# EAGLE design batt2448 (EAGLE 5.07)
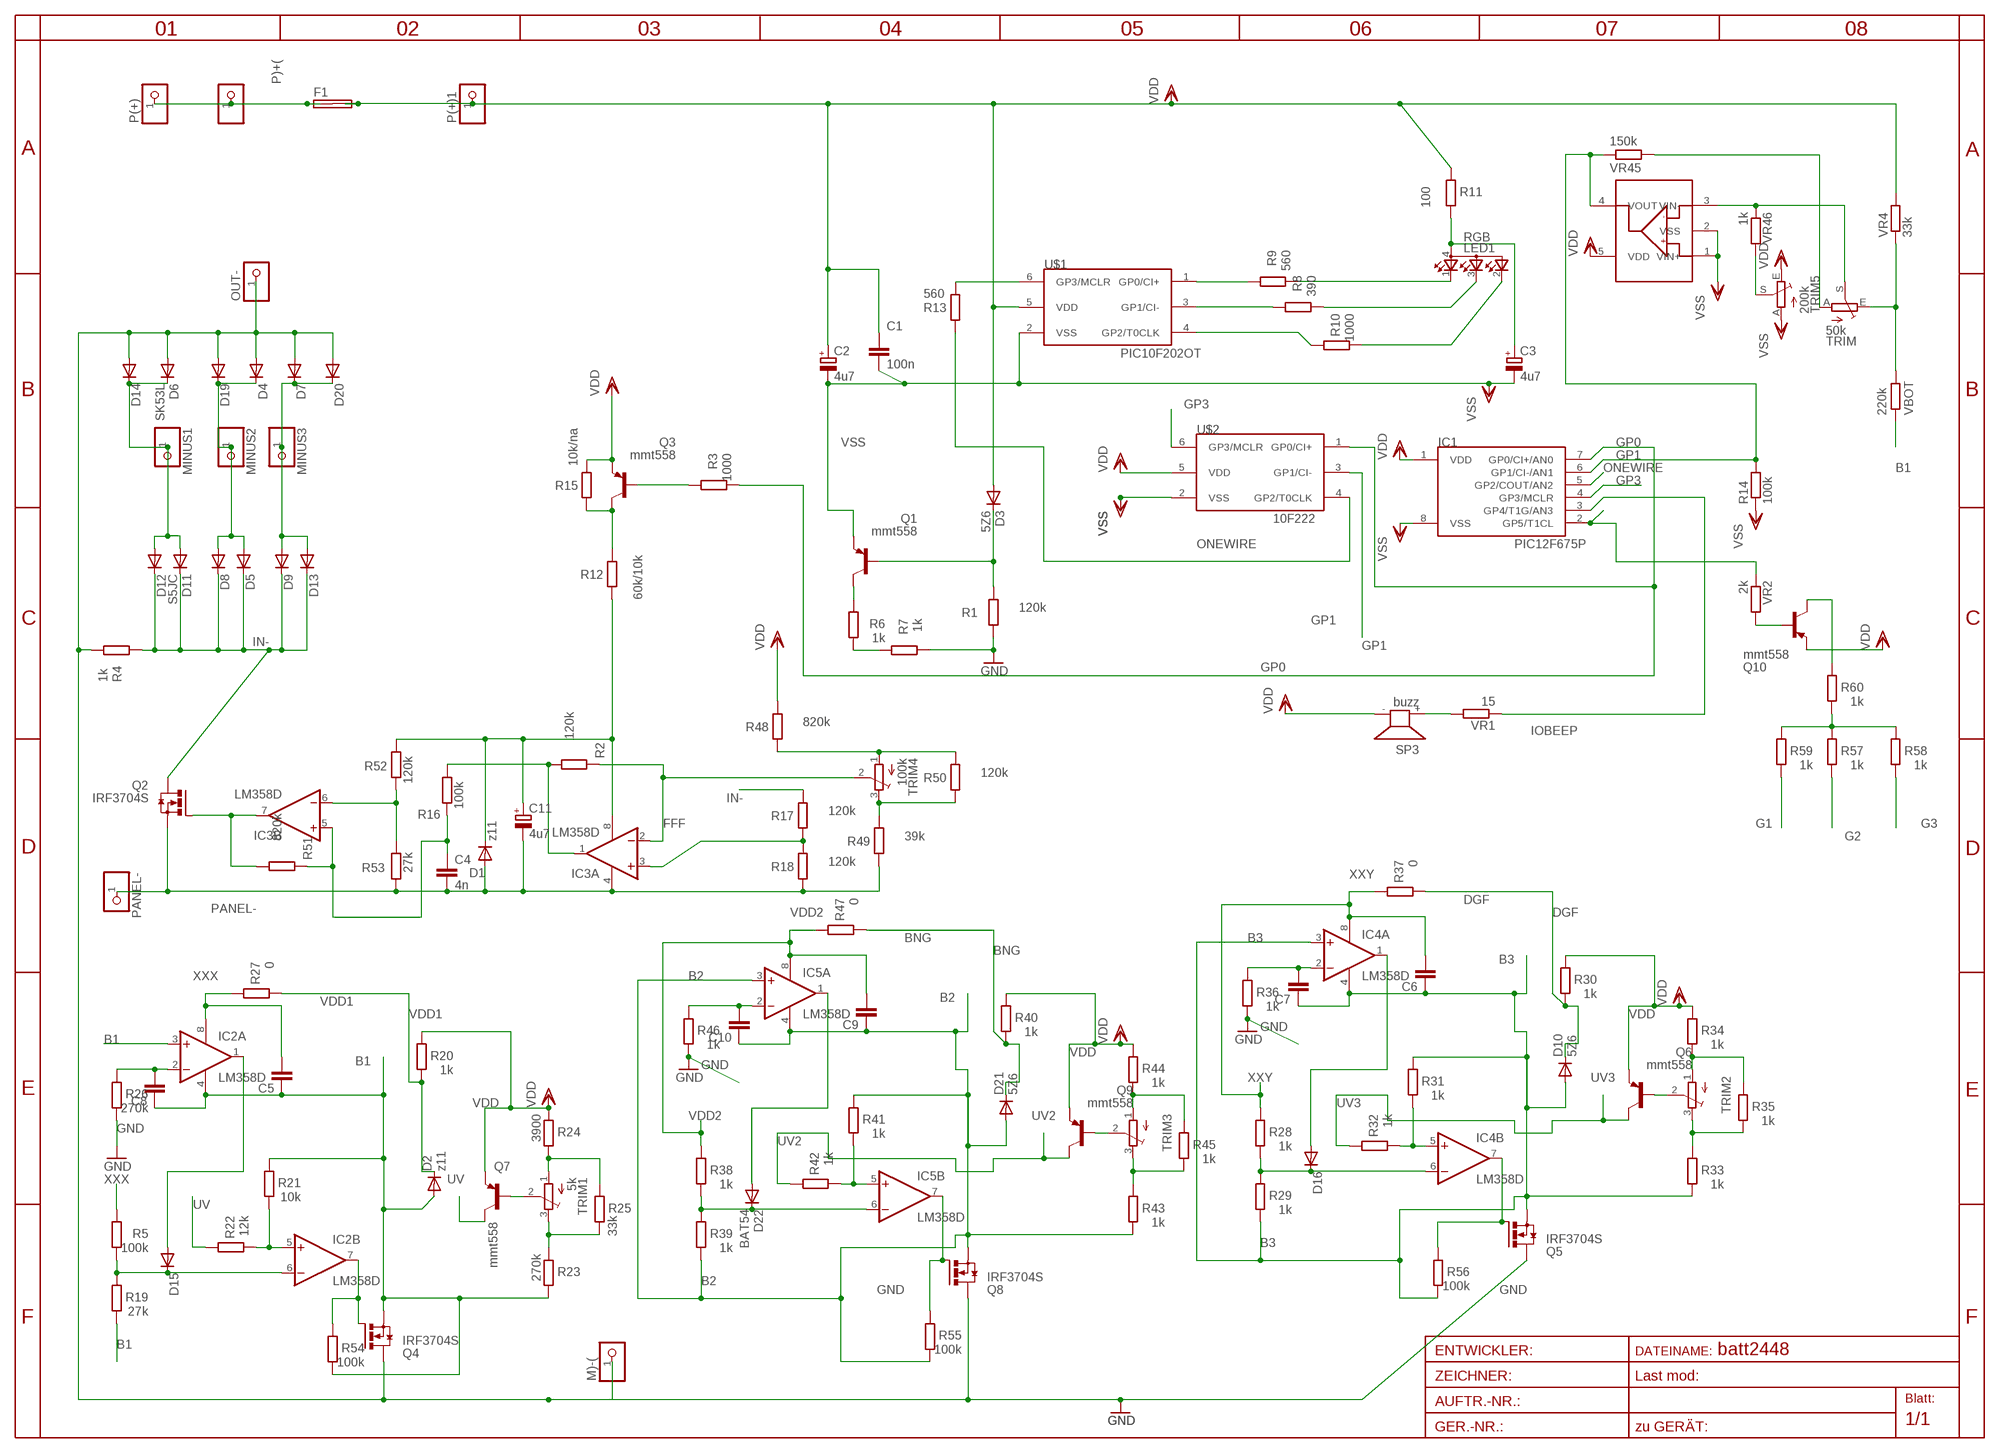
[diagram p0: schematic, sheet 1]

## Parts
C1  100n  C-EUC1206  [C1206]
C2  4u7  CPOL-EUSMCA  [SMC_A]
C3  4u7  CPOL-EUSMCA  [SMC_A]
C4  4n  C-EUC0805  [C0805]
C5  C-EUC1206  [C1206]
C6  C-EUC1206  [C1206]
C7  C-EUC0805  [C0805]
C8  C-EUC0805  [C0805]
C9  C-EUC1206  [C1206]
C10  C-EUC0805  [C0805]
C11  4u7  CPOL-EUSANYO_SMD_B6  [SANYO-OSCON_SMD_B6]
D1  z11  DIODE-MINIMELF  [MINIMELF]
D2  z11  DIODE-MINIMELF  [MINIMELF]
D3  5Z6  DIODE-MINIMELF  [MINIMELF]
D4  DIODE-SMC  [SMC]
D5  DIODE-SMC  [SMC]
D6  SK53L  DIODE-SMC  [SMC]
D7  DIODE-SMC  [SMC]
D8  DIODE-SMC  [SMC]
D9  DIODE-SMC  [SMC]
D10  5Z6  DIODE-MINIMELF  [MINIMELF]
D11  S5JC  DIODE-SMC  [SMC]
D12  DIODE-SMC  [SMC]
D13  DIODE-SMC  [SMC]
D14  DIODE-SMC  [SMC]
D15  DIODE-MINIMELF  [MINIMELF]
D16  DIODE-MINIMELF  [MINIMELF]
D19  DIODE-SMC  [SMC]
D20  DIODE-SMC  [SMC]
D21  5Z6  DIODE-MINIMELF  [MINIMELF]
D22  BAT54  DIODE-MINIMELF  [MINIMELF]
F1  SHK20L7MM5  [7MM5]
IC1  PIC12F675P  [DIL8]
IC2  LM358D  [SO08]
IC3  LM358D  [SO08]
IC4  LM358D  [SO08]
IC5  LM358D  [SO08]
IC6  MCP6001U  [SOT23-5L]
LED1  RGB  GM1WA55311A  [FULL3528]
M)-(  PINHD-1X11X0.4  [1X01]
MINUS1  PINHD-1X12MM3  [1X2MM3]
MINUS2  PINHD-1X12MM3  [1X2MM3]
MINUS3  PINHD-1X12MM3  [1X2MM3]
OUT-  PINHD-1X12MM3  [1X2MM3]
P(+)  PINHD-1X14.5MM  [1X4MM5]
P(+)1  PINHD-1X14.5MM  [1X4MM5]
P)+(  PINHD-1X11X0.4  [1X01]
PANEL-  PINHD-1X12MM3  [1X2MM3]
Q1  mmt558  BC857ALT1SMD  [SOT23-BEC]
Q2  IRF3704S  [D2PACK]
Q3  mmt558  BC857ALT1SMD  [SOT23-BEC]
Q4  IRF3704S  [D2PACK]
Q5  IRF3704S  [D2PACK]
Q6  mmt558  BC857ALT1SMD  [SOT23-BEC]
Q7  mmt558  BC857ALT1SMD  [SOT23-BEC]
Q8  IRF3704S  [D2PACK]
Q9  mmt558  BC857ALT1SMD  [SOT23-BEC]
Q10  mmt558  BC857ALT1SMD  [SOT23-BEC]
R1  120k  R-EU_R1206  [R1206]
R2  120k  R-EU_R0805  [R0805]
R3  1000  R-EU_R0805  [R0805]
R4  1k  R-EU_0207/25  [0207/25]
R5  100k  R-EU_R1206  [R1206]
R6  1k  R-EU_R1206  [R1206]
R7  1k  R-EU_R1206  [R1206]
R8  390  R-EU_R0805  [R0805]
R9  560  R-EU_R0805  [R0805]
R10  1000  R-EU_R0805  [R0805]
R11  100  R-EU_R1206  [R1206]
R12  60k/10k  R-EU_R1206  [R1206]
R13  560  R-EU_R0805  [R0805]
R14  100k  R-EU_R1206  [R1206]
R15  10k/na  R-EU_R0805  [R0805]
R16  100k  R-EU_R0805  [R0805]
R17  120k  R-EU_R0805  [R0805]
R18  120k  R-EU_R0805  [R0805]
R19  27k  R-EU_R0805  [R0805]
R20  1k  R-EU_R1206  [R1206]
R21  10k  R-EU_R0805  [R0805]
R22  12k  R-EU_R1206  [R1206]
R23  270k  R-EU_R0805  [R0805]
R24  3900  R-EU_R0805  [R0805]
R25  33k  R-EU_R0805  [R0805]
R26  270k  R-EU_R1206  [R1206]
R27  0  R-EU_R1203  [R1203]
R28  1k  R-EU_R1206  [R1206]
R29  1k  R-EU_R0805  [R0805]
R30  1k  R-EU_R1206  [R1206]
R31  1k  R-EU_R0805  [R0805]
R32  1k  R-EU_R1206  [R1206]
R33  1k  R-EU_R0805  [R0805]
R34  1k  R-EU_R0805  [R0805]
R35  1k  R-EU_R0805  [R0805]
R36  1k  R-EU_R1206  [R1206]
R37  0  R-EU_R1203  [R1203]
R38  1k  R-EU_R1206  [R1206]
R39  1k  R-EU_R0805  [R0805]
R40  1k  R-EU_R1206  [R1206]
R41  1k  R-EU_R0805  [R0805]
R42  1k  R-EU_R1206  [R1206]
R43  1k  R-EU_R0805  [R0805]
R44  1k  R-EU_R0805  [R0805]
R45  1k  R-EU_R0805  [R0805]
R46  1k  R-EU_R1206  [R1206]
R47  0  R-EU_R1203  [R1203]
R48  820k  R-EU_R0805  [R0805]
R49  39k  R-EU_R1206  [R1206]
R50  120k  R-EU_R0805  [R0805]
R51  820k  R-EU_R0805  [R0805]
R52  120k  R-EU_R1206  [R1206]
R53  27k  R-EU_R1206  [R1206]
R54  100k  R-EU_R0805  [R0805]
R55  100k  R-EU_R0805  [R0805]
R56  100k  R-EU_R0805  [R0805]
R57  1k  R-EU_0207-17MM5  [0207/17MM5]
R58  1k  R-EU_0207-17MM5  [0207/17MM5]
R59  1k  R-EU_0207/10  [0207/10]
R60  1k  R-EU_R0805  [R0805]
SP3  buzz  KSS12017MM  [KSS1202]
TRIM  50k  TRIM_EU-S64W  [S64W]
TRIM1  5k  TRIM_EU-3223G  [3223G]
TRIM2  TRIM_EU-3223G  [3223G]
TRIM3  TRIM_EU-3223G  [3223G]
TRIM4  100k  TRIM_EU-3223G  [3223G]
TRIM5  200k  TRIM_EU-S64W  [S64W]
U$1  PIC10F202OT  [SOT23-6]
U$2  10F222  PIC10F204OT  [SOT23-6]
VBOT  220k  R-EU_R0805  [R0805]
VR1  15  R-EU_R0805  [R0805]
VR2  2k  R-EU_R0805  [R0805]
VR4  33k  R-EU_R1206  [R1206]
VR45  150k  R-EU_R0805  [R0805]
VR46  1k  R-EU_R0805  [R0805]

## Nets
A: C3.+ LED1.4(A) R11.1
B: LED1.3(CBLUE) R8.1
B1: C5.1 C8.1 D2.A D6.C D11.A D12.A D14.C IC2.3(A:+IN) IC2.4(P:V-) MINUS1.1 Q4.3(S) R19.1 R21.2 R23.1 R54.1 VBOT.1
B2: C9.1 C10.1 D7.C D9.A D13.A D20.C D21.A IC5.3(A:+IN) IC5.4(P:V-) MINUS3.1 Q8.3(S) R39.1 R41.2 R43.1 R55.1
B3: C6.1 C7.1 D4.C D5.A D8.A D10.A D19.C IC4.3(A:+IN) IC4.4(P:V-) MINUS2.1 Q5.3(S) R29.1 R31.2 R33.1 R56.1
BNG: D21.C R40.1 R47.1
BUZZ+: SP3.+ VR1.2
DGF: D10.C R30.1 R37.1
DIGOUT: R57.2 R58.2 R59.2 R60.1
FFF: IC3.2(A:-IN) R2.2 TRIM4.2(S)
G: LED1.2(CGREEN) R10.1
G1: IC2.7(B:OUT) Q4.1(G) R54.2 R59.1
G2: IC5.7(B:OUT) Q8.1(G) R55.2 R57.1
G3: IC4.7(B:OUT) Q5.1(G) R56.2 R58.1
GND: D4.A D6.A D7.A D14.A D19.A D20.A M)-(.1 OUT-.1 Q4.2(D) Q5.2(D) Q8.2(D) R1.2 R4.1 R7.1 R26.1 R36.1 R46.1
GP0: IC1.7(GP0/CI+/AN0) R3.1 U$2.1(GP0/CI+)
GP0C: R9.2 U$1.1(GP0/CI+)
GP1: IC1.6(GP1/CI-/AN1) IC6.4(VOUT) R14.2 U$2.3(GP1/CI-) VR45.1
GP1C: R8.2 U$1.3(GP1/CI-)
GP2C: R10.2 U$1.4(GP2/T0CLK)
GP3: IC1.4(GP3/MCLR) U$2.6(GP3/MCLR)
GP3_2: R13.1 U$1.6(GP3/MCLR)
IN+: F1.1A F1.1B P(+).1 P)+(.1
IN-: D5.C D8.C D9.C D11.C D12.C D13.C Q2.2(D) R4.2 R17.1
IOBEEP: IC1.3(GP4/T1G/AN3) VR1.1
N$1: D15.C IC2.6(B:-IN) R5.1 R19.2
N$2: D3.C Q1.B R1.1
N$4: C11.+ D1.C IC3.8(P:V+) R12.2 R52.1
N$5: TRIM.E VBOT.2 VR4.1
N$6: Q1.C R6.2
N$7: TRIM5.S VR46.2
N$8: Q3.B R3.2
N$9: Q10.B VR2.2
N$10: IC2.5(B:+IN) R21.1 R22.1
N$11: Q3.C R12.1 R15.2
N$12: TRIM.A VR45.2
N$13: IC3.1(A:OUT) R2.1 R16.1
N$14: IC6.3(VIN-) TRIM.S VR46.1
N$16: IC3.3(A:+IN)
N$17: D15.A IC2.1(A:OUT)
N$18: R6.1 R7.2
N$19: R17.2 R18.1
N$20: C8.2 IC2.2(A:-IN) R26.2
N$21: Q7.B TRIM1.2(S)
N$22: R24.1 R25.2 TRIM1.1(A)
N$23: R23.2 R25.1 TRIM1.3(E)
N$24: IC3.6(B:-IN) R52.2 R53.1
N$25: D16.C IC4.6(B:-IN) R28.1 R29.2
N$26: IC4.5(B:+IN) R31.1 R32.1
N$27: Q6.B TRIM2.2(S)
N$30: R34.1 R35.2 TRIM2.1(A)
N$31: R33.2 R35.1 TRIM2.3(E)
N$32: D16.A IC4.1(A:OUT)
N$33: C7.2 IC4.2(A:-IN) R36.2
N$34: Q10.C R60.2
N$35: D22.C IC5.6(B:-IN) R38.1 R39.2
N$36: IC5.5(B:+IN) R41.1 R42.1
N$37: Q9.B TRIM3.2(S)
N$38: IC1.2(GP5/T1CL) VR2.1
N$39: R44.1 R45.2 TRIM3.1(A)
N$40: R43.2 R45.1 TRIM3.3(E)
N$41: D22.A IC5.1(A:OUT)
N$42: C10.2 IC5.2(A:-IN) R46.2
N$43: R49.1 R50.2 TRIM4.3(E)
N$45: R48.2 R50.1 TRIM4.1(A)
N$46: C4.1 IC3.5(B:+IN) R16.2 R51.2
N$47: IC3.7(B:OUT) Q2.1(G) R51.1
ONEWIRE: IC1.5(GP2/COUT/AN2) R13.2 U$2.4(GP2/T0CLK)
PANEL-: C4.2 C11.- D1.A IC3.4(P:V-) PANEL-.1 Q2.3(S) R18.2 R49.2 R53.2
R: LED1.1(CRED) R9.1
UV: Q7.C R22.2
UV2: Q9.C R42.2
UV3: Q6.C R32.2
VDD: C1.1 C2.+ D3.A F1.2A F1.2B IC1.1(VDD) IC6.5(VDD) P(+)1.1 Q3.E Q6.E Q7.E Q9.E Q10.E R11.2 R15.1 R20.2 R24.2 R30.2 R34.2 R40.2 R44.2 R48.1 SP3.- TRIM5.E U$1.5(VDD) U$2.5(VDD) VR4.2
VDD1: D2.C R20.1 R27.1
VDD2: C9.2 IC5.8(P:V+) R38.2 R47.2
VSS: C1.2 C2.- C3.- IC1.8(VSS) IC6.1(VIN+) IC6.2(VSS) Q1.E R14.1 TRIM5.A U$1.2(VSS) U$2.2(VSS)
XXX: C5.2 IC2.8(P:V+) R5.2 R27.2
XXY: C6.2 IC4.8(P:V+) R28.2 R37.2

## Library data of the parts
C1 C4-C10 = rcl:C-EU: CAPACITOR, European symbol
C2 C3 C11 = rcl:CPOL-EU: POLARIZED CAPACITOR, European symbol
D1-D16 D19-D22 = diode:DIODE-: DIODE
F1 = fuse:SHK20L: FUSE HOLDER 5 x 20 mm, SH contact, SHH1 Schukat, E1073 Buerklin
IC1 = microchip-3:PIC12F6*: uPC nW 1k Program Flash memory 2x Timer Comparator 10b A/D converter/ 4xIN
IC2-IC5 = linear:LM358: OP AMP also LM158; LM258; LM2904 Source: http://cache.national.com/ds/LM/LM158.pdf
IC6 = microchip-3:MCP6001U
LED1 = led:GM1WA55311A: Chip LED RGB Source: http://document.sharpsma.com/files/GM1WA55311A_SS.pdf
M)-( MINUS1-MINUS3 OUT- P(+) P(+)1 P)+( PANEL- = pinhead:PINHD-1X1: PIN HEADER
Q1 Q3 Q6 Q7 Q9 Q10 = transistor-pnp:BC857*: PNP Transistror
Q2 Q4 Q5 Q8 = transistor-power:IRF3704: SMPS MOSFET HEXFET® Power MOSFET Source: http://www.irf.com/product-info/datasheets/data/irf3704.pdf
R1-R13 R15-R21 R23-R26 R28-R36 R38-R46 R48-R60 VBOT VR1 VR2 VR4 VR45 VR46 = rcl-2:R-EU_: RESISTOR, European symbol
R14 R22 R27 R37 R47 = rcl:R-EU_: RESISTOR, European symbol
SP3 = buzzer:KSS1201: SPEAKER
TRIM TRIM1-TRIM5 = pot:TRIM_EU-: POTENTIOMETER
U$1 U$2 = microchip-3:PIC10F2*: uPC nW 0,25/0,5k Program Flash memory Comparator

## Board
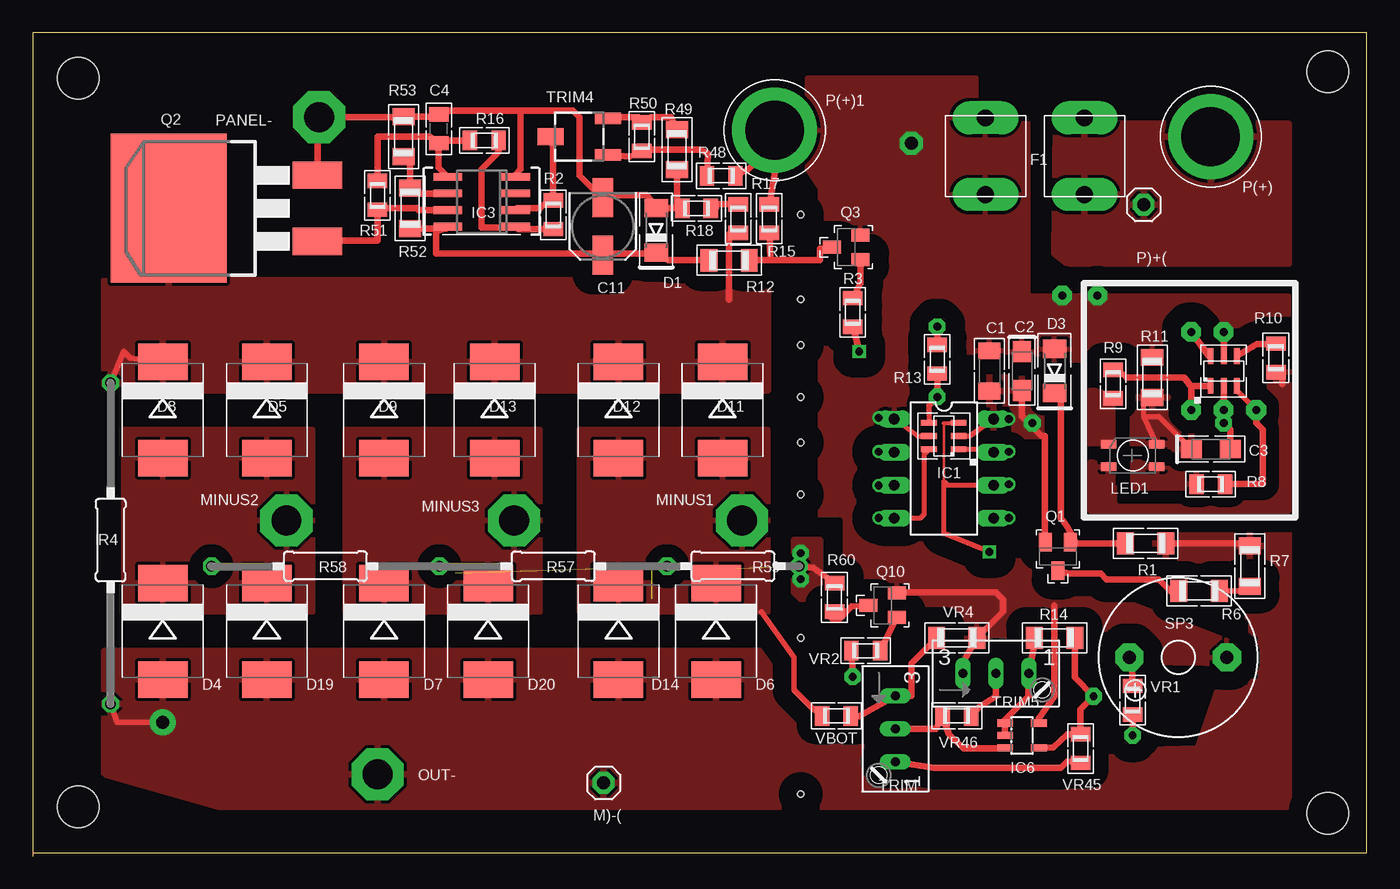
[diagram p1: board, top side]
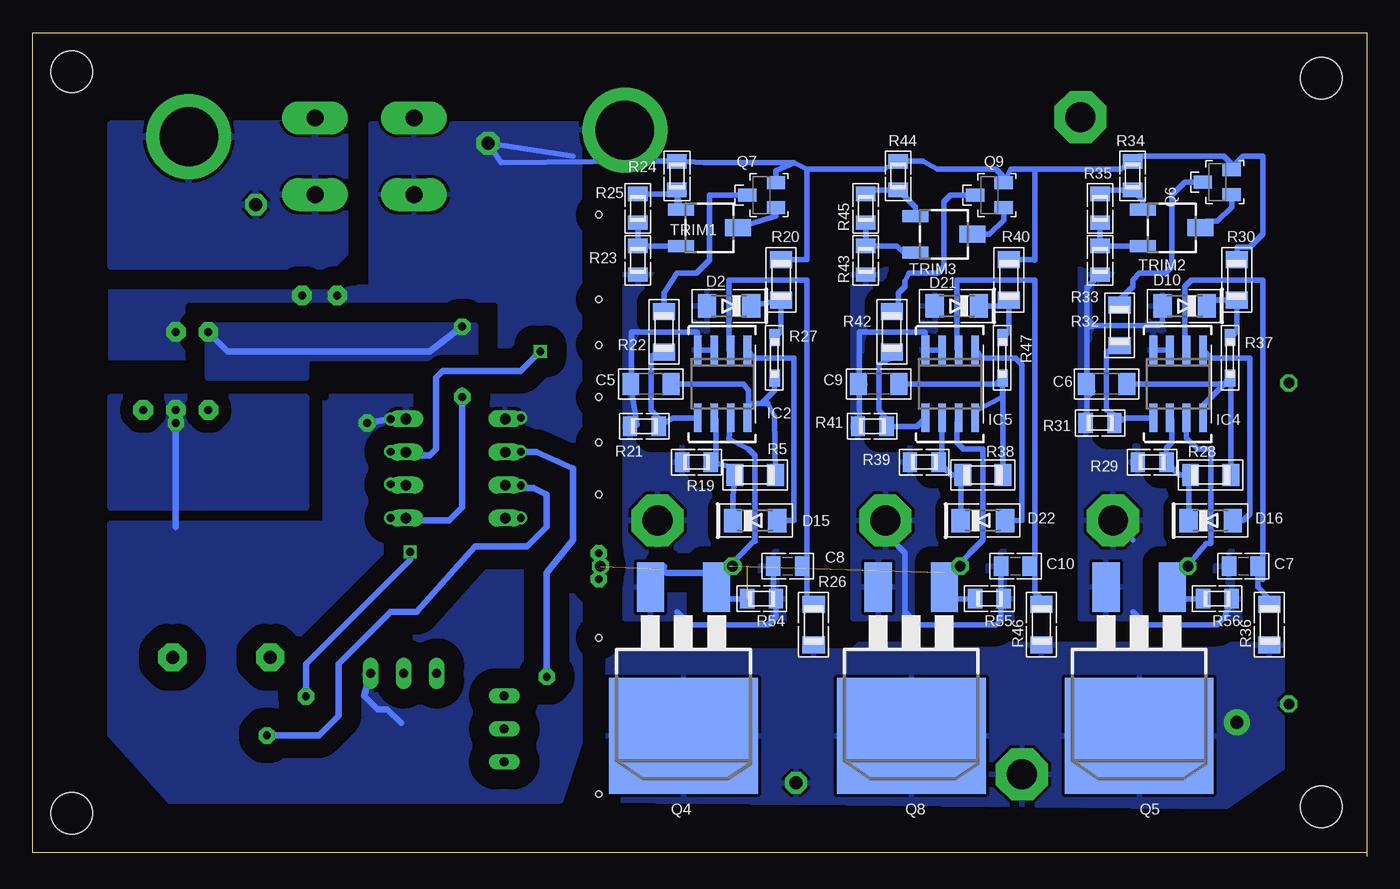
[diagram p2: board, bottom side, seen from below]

Size 102.5 x 63.3 mm. Coordinates in mm from the lower left corner, seen from the top.
Outline: 0,0.3 102.5,0.3 102.5,63.3 0,63.3 0,0
Copper layers (1*16): Top 0.035mm / dielectric 1.5mm / Bottom 0.035mm
Design rules "default *": minimum track width 8mil, minimum drill 4mil, track to track 8mil, track to pad 8mil, pad to pad 8mil, via to via 8mil, smd to smd 8mil, copper to edge 1mm, drill to drill 2mil, minimum pad ring 10mil, minimum via ring 8mil, stop-mask expansion 4mil, vias tented up to drill 0mil, thermal gap 10mil
Holes 3.2 mm at 3.5,59.8 3.5,3.8 99.5,60.3 99.5,3.3
Holes 0.5 mm at 59,27.8 59,31.8 59,35.3 59,39.3 59,16.8 59,4.8 59,42.8 59,49.3

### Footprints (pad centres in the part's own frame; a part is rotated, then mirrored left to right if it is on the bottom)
C1206 = smd 1.3 x 1.7: 1 -1.55,0; 2 1.55,0
SMC_A = smd 1.6 x 1.4: + -1.5,0; - 1.5,0
C0805 = smd 1.1 x 1.5: 1 -1.1,0; 2 1.1,0
SANYO-OSCON_SMD_B6 = smd 3 x 1.6: + 2.2,0; - -2.2,0
MINIMELF = smd 1.4 x 1.8: A 1.7,0; C -1.7,0
SMC = smd 2.8 x 3.8: A 3.7,0; C -3.7,0
7MM5 = drill 1.3 pad 2.54 long: 1A -3.8,2.94; 1B -3.8,-2.94; 2A 3.8,2.94; 2B 3.8,-2.94
DIL8 = drill 0.813 long: 1 -3.81,-3.81; 2 -1.27,-3.81; 3 1.27,-3.81; 4 3.81,-3.81; 5 3.81,3.81; 6 1.27,3.81; 7 -1.27,3.81; 8 -3.81,3.81
SO08 = smd 0.6 x 2.2: 1 -1.905,-2.6; 2 -0.635,-2.6; 3 0.635,-2.6; 4 1.905,-2.6; 5 1.905,2.6; 6 0.635,2.6; 7 -0.635,2.6; 8 -1.905,2.6
SOT23-5L = smd 0.55 x 1.2: 1 -0.95,-1.3; 2 0,-1.3; 3 0.95,-1.3; 4 0.95,1.3; 5 -0.95,1.3
FULL3528 = smd 0.65 x 1.2: 1 0.875,1.85; 2 -0.875,1.85; 3 -0.875,-1.85; 4 0.875,-1.85
1X01 = drill 1 pad 1.676 octagon: 1 0,0
1X2MM3 = drill 2.3 pad 4 octagon: 1 0,0
1X4MM5 = drill 4.5 pad 6.35 round: 1 0,0
SOT23-BEC = smd 1 x 1.4: B -0.95,-1.1; C 0,1.1; E 0.95,-1.1
D2PACK = smd 2.083 x 3.81: 1 -2.54,-8.89; 3 2.54,-8.89 | smd 11.43 x 8.89: 2 0,2.54
R1206 = smd 1.3 x 1.7: 1 -1.55,0; 2 1.55,0
R0805 = smd 1.1 x 1.5: 1 -1.1,0; 2 1.1,0
0207/25 = drill 0.813 octagon: 1 -12.58,0; 2 12.08,0
R1203 = smd 1.3 x 0.8: 1 -1.55,0; 2 1.55,0
0207/17MM5 = drill 0.813 octagon: 1 -8.75,0; 2 8.75,0
0207/10 = drill 0.813 octagon: 1 -5.08,0; 2 5.08,0
KSS1202 = drill 1 pad 2.159 octagon: + 3.75,0; - -3.75,0
S64W = drill 0.7 long: A 2.54,1.27; E -2.54,1.27; S 0,1.27
3223G = smd 2 x 0.9: 1 -2.2,1.4; 3 -2.2,-1.4 | smd 2 x 1.3: 2 2.2,0
SOT23-6 = smd 0.45 x 1.2: 1 -1.016,-1.15; 2 0,-1.15; 3 1.016,-1.15; 4 1.016,1.15; 5 0,1.15; 6 -1.016,1.15

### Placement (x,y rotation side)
C1  73.5,37.3 270 top
C2  76,37.3 270 top
C3  90.5,31.3 0 top
C4  31.2,55.9 90 top
C5  55,36.3 0 bottom
C6  20,36.3 0 bottom
C7  9.5,22.3 0 bottom
C8  44.5,22.3 0 bottom
C9  37.5,36.3 0 bottom
C10  27,22.3 0 bottom
C11  43.8,48.4 270 top
D1  47.9,48.1 90 top
D2  49,42.3 180 bottom
D3  78.5,37.3 90 top
D4  10,17.3 270 top
D5  18,34.3 270 top
D6  52.5,17.3 270 top
D7  27,17.3 270 top
D8  10,34.3 270 top
D9  27,34.3 270 top
D10  14,42.3 180 bottom
D11  53,34.3 270 top
D12  45,34.3 270 top
D13  35.5,34.3 270 top
D14  45,17.3 270 top
D15  47,25.8 0 bottom
D16  12,25.8 0 bottom
D19  18,17.3 270 top
D20  35,17.3 270 top
D21  31.5,42.3 180 bottom
D22  29.5,25.8 0 bottom
F1  77,53.8 180 top
IC1  70,29.8 270 top
IC2  49.5,36.3 180 bottom
IC3  34.5,50.3 90 top
IC4  14.5,36.3 180 bottom
IC5  32,36.3 180 bottom
IC6  76,9.3 270 top
LED1  84.5,30.8 90 top
M)-(  43.87,5.65 0 top
MINUS1  54.5,25.8 180 top
MINUS2  19.5,25.8 180 top
MINUS3  37,25.8 180 top
OUT-  26.5,6.3 180 top
P(+)  90.5,55.3 0 top
P(+)1  57,55.8 0 top
P)+(  85.34,50.07 0 top
PANEL-  22,56.8 180 top
Q1  78.75,23.05 180 top
Q2  13,49.8 90 top
Q3  62.5,46.8 90 top
Q4  52.5,11.8 180 bottom
Q5  17.5,11.8 180 bottom
Q6  11.5,51.8 90 bottom
Q7  46.5,50.8 90 bottom
Q8  35,11.8 180 bottom
Q9  29,50.8 90 bottom
Q10  65.3,19.3 90 top
R1  85.5,24.05 0 top
R2  40,49.3 90 top
R3  63,41.8 90 top
R4  6,24.3 90 top
R5  47,29.3 0 bottom
R6  89.6,20.4 180 top
R7  93.5,22.3 270 top
R8  90.5,28.6 0 top
R9  83,36.3 90 top
R10  95.5,38.3 90 top
R11  86,36.8 90 top
R12  53.5,45.8 180 top
R13  69.5,38.2 270 top
R14  78.5,16.8 0 top
R15  56.6,49 270 top
R16  34.7,55 180 top
R17  54.2,49 90 top
R18  51,49.8 180 top
R19  51.5,30.3 0 bottom
R20  45,44.3 90 bottom
R21  55.5,33.05 180 bottom
R22  54,40.3 90 bottom
R23  56,45.8 90 bottom
R24  53,52.3 90 bottom
R25  56,49.8 90 bottom
R26  42.5,17.8 90 bottom
R27  45.5,38.3 270 bottom
R28  12,29.3 0 bottom
R29  16.5,30.3 0 bottom
R30  10,44.3 90 bottom
R31  20.5,33.3 180 bottom
R32  19,40.8 90 bottom
R33  20.5,45.8 90 bottom
R34  18,52.3 90 bottom
R35  20.5,49.8 90 bottom
R36  7.5,17.8 90 bottom
R37  10.5,38.3 270 bottom
R38  29.5,29.3 0 bottom
R39  34,30.3 0 bottom
R40  27.5,44.3 90 bottom
R41  38,33.05 180 bottom
R42  36.5,40.3 90 bottom
R43  38.5,45.8 90 bottom
R44  36,52.3 90 bottom
R45  38.5,49.8 90 bottom
R46  25,17.8 90 bottom
R47  28,38.3 270 bottom
R48  52.9,52.3 180 top
R49  49.5,54.3 270 top
R50  46.8,55.3 90 top
R51  26.5,50.8 90 top
R52  29,49.8 90 top
R53  28.5,55.3 90 top
R54  46.5,19.8 180 bottom
R55  29,19.8 180 bottom
R56  11.5,19.8 180 bottom
R57  40,22.3 0 top
R58  22.5,22.3 0 top
R59  53.8,22.3 0 top
R60  61.6,19.9 270 top
SP3  88,15.3 180 top
TRIM  65,9.8 270 top
TRIM1  50.5,48.3 0 bottom
TRIM2  15,48.3 0 bottom
TRIM3  32.5,47.8 0 bottom
TRIM4  42,55.3 180 top
TRIM5  74,12.8 0 top
U$1  91.5,37.3 0 top
U$2  70,32.3 90 top
VBOT  61.75,10.8 0 top
VR1  84.5,12 90 top
VR2  64,15.8 0 top
VR4  71,16.8 0 top
VR45  80.5,8.3 270 top
VR46  71,10.8 0 top

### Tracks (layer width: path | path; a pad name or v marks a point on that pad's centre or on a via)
A
  Top 0.4: 85.35,33.8 85.35,35.1 R11.1 | LED1.4 85.35,33.8 | C3.+ 86.5,33.8 85.35,33.8
  pour Top (isolate 1, rank 2): 84.5,35.8 89.5,35.8 89.5,31.3 84.5,31.3
B
  pour Top (isolate 1.016): 84.5,30.3 86,30.3 86.5,29.8 90.5,29.8 90.5,28.3 84.5,28.3
B1
  Top 0.406: VBOT.1 60,11.3 58.5,12.8 58.5,15.3 56,18.8
  Bottom 0.406: IC2.3 IC2.4 51.41,40.2 51.5,40.3 56.5,40.3 56.5,36.75 C5.1 56.05,33.15 R21.2 | 53,18.8 52,17.8 46,17.8 45.4,18.4 R54.1 45.6,20.6 C8.1
  pour Top (isolate 1, rank 2): 56.5,18.8 42,18.8 42,32.8 56.5,32.8
  pour Bottom (isolate 1.25, rank 4): 57,18.3 42.5,18.3 42.5,45.3 57,45.3
B2
  Bottom 0.406: IC5.3 IC5.4 33.91,40.2 34,40.3 39,40.3 39,36.75 C9.1 38.55,36.25 39,35.8 39,33.45 R41.2 | 35.5,18.8 35.5,18.3 | 35.5,18.8 35.5,23.3 36,23.8 MINUS3.1 | 28.1,20.1 C10.1 | 28.1,20.1 R55.1 | 28.1,20.1 28.1,18.2 28.5,17.8 34.5,17.8 35.5,18.8
  pour Top (isolate 1, rank 3): 24,18.8 24,32.8 39,32.8 39,18.8
  pour Bottom (isolate 1.25, rank 3): 24,18.3 24,45.3 39.5,45.3 39.5,18.3
B3
  Bottom 0.406: D10.A 15.7,41.1 16,40.8 21,40.8 | 21,40.8 21.5,41.3 21.5,43.7 R33.1 | 18,24.3 MINUS2.1 | IC4.3 IC4.4 | 21,40.8 21.1,40.7 21.4,40.7 21.5,40.8 21.5,36.75 C6.1 21.05,35.75 21.5,35.3 21.5,33.7 R31.2 | R56.1 10.9,18.4 11.5,17.8 17,17.8 18,18.8
  pour Top (isolate 1, rank 4): 7,18.8 7,32.8 21.5,32.8 21.5,18.8
  pour Bottom (isolate 1.25, rank 4): 6.5,18.3 6.5,45.3 22,45.3 22,18.3
BNG
  Bottom 0.406: R47.1 27.95,39.85 27.5,40.3 R40.1 27.95,42.3 D21.C
BUZZ+
  Top 0.5: VR1.2 84.39,15.16 SP3.+
DGF
  Bottom 0.406: R37.1 10,40.35 R30.1 11.85,42.75 D10.C
DIGOUT  (via drill 0.6 pad 1.27)  (3 unrouted)
  Top 0.5: R60.1 60,22.15 R59.2
  Bottom 0.406: R58.2 32,22.3 32.5,21.8 | 49.5,21.8 49,22.3
  Bottom 0.5: 49.5,21.8 53.8,21.8 54.1,22.1 54,22.3
  other vias: 59,21.3 59,23.3
  pour Top (isolate 1.5): 58.5,24.3 60.5,24.3 60.5,19.8 59,19.8 58.5,20.3
FFF
  Top 0.5: TRIM4.2 40,54.6 R2.2 39.6,50.4 39,49.8 37.23,49.8 IC3.2
G
  Top 0.5: R10.1 96,37.2 96,36.3
  pour Top (isolate 1, rank 2): 81.25,30.3 83,30.3 83,28.3 95,28.3 95,37.8 96.5,37.8 96.5,26.55 81.25,26.55
G1  (2 unrouted)
  Bottom 0.406: IC2.7 49,32.06 47.5,31.3 47,30.8 47,24.19 47.11,24.19 48.5,22.8 48.5,22.65 R59.1 | R54.2 49.46,19.8 Q4.1
G2
  Bottom 0.406: IC5.7 31.36,33.43 31.5,33.3 31.5,31.8 31,31.3 29.5,31.3 29.5,24.3 30.5,23.3 30.97,22.78 | 30.97,22.78 31.85,21.8 Q8.1 31.57,19.8 R55.2 | R57.1 30.75,22.55 30.97,22.78
G3
  Bottom 0.406: IC4.7 13.87,32.16 13,31.3 12,31.3 12,24.05 12.32,24.05 13.2,23.05 R58.1 14.5,22.3 15,21.8 15,20.73 Q5.1 14.07,19.8 R56.2
GND  (via drill 1 pad 2)
  Top 0.406: v10,10.3 6.5,10.3 R4.1 | 93.5,24.05 R7.1
  Top 0.5: R1.2 93.5,24.05
  pour Top (isolate 1.422, rank 5): 96.5,3.8 14.3,3.8 5.5,6.3 5.5,15.8 72.5,15.8 72.5,7.8 89.5,8.3 94,21.3 86,21.3 86,24.8 96.5,24.8
  pour Bottom (isolate 1.422, rank 4): 58.3,4.3 10.8,3.8 6.5,6.8 6.5,16.3 39,16.3 39.5,15.8 58.3,15.8
GP0  (via drill 0.6, 0.6 pad 1)
  Top 0.4: U$2.1 73.6,31.28 IC1.7
  Top 0.406: v75,31.1 73.84,31.1 IC1.7
  Top 0.5: R3.1 v63.5,38.8
  Bottom 0.5: v75,31.1 75.2,31.3 | v63.5,38.8 65,37.3 71,37.3 71.5,36.8 71.5,31.3 72,30.8 73.54,30.8 IC1.7
GP0C  (via drill 0.6 pad 1.5)
  Top 0.4: R9.2 83.4,37.4 84,36.8
  Top 0.5: 89,36.05 v89,34.3 | 84,36.8 88.47,36.8 89,36.05 | U$1.1 89.1,36.15 89,36.05
GP1  (via drill 0.6, 0.6 pad 1, 0.6 pad 1.27)
  Top 0.2: 70,28.8 70,33.3
  Top 0.3: 70,33.3 71.13,33.3
  Top 0.4: IC1.6 70.27,28.53 70,28.8 70,24.8 v73.5,23.4
  Top 0.406: IC1.6 74.93,28.53 v75,28.6 | 71.13,33.3 U$2.3
  Top 0.5: IC6.4 77.55,8.35 78.4,8.4 79.5,9.4 VR45.1 80.5,11.3 v81.5,12.3 80.05,13.75 R14.2 80,16.75
  Bottom 0.5: v81.5,12.3 81.5,14.8 73.5,22.8 v73.5,23.4
GP1C  (via drill 0.6 pad 1.5)
  Top 0.4: U$1.3 92.52,35.78 v94,34.3
  Top 0.5: v94,34.3 94,33.3 94.5,32.8 94.5,28.6 R8.2
GP2C
  Top 0.5: U$1.4 94.05,39.35 95.5,39.35 R10.2
GP3  (via drill 0.6 pad 1)
  Top 0.4: IC1.4 68.19,25.99 68.5,26.3 68.5,30.93 U$2.6
  Top 0.406: IC1.4 v65.01,25.99 v65,26
GP3_2  (via drill 0.6 pad 1.27, 0.6 pad 1.5)
  Top 0.5: U$1.6 90.35,38.45 v89,40.3 | R13.1 v69.5,40.7
  Bottom 0.5: v89,40.3 87.5,38.8 72,38.8 v69.5,40.7
  pour Bottom (isolate 1): 68.5,40.8 89,40.8 89,38.3 89,36.8 81.5,36.8 81.5,38.3 68.5,38.3
IN+
  pour Top (isolate 1.5): 78.6,56.3 96.5,56.3 96.5,45.55 79.5,45.55 78.5,46.3
  pour Bottom (isolate 1.5): 78.5,56.3 96.5,56.3 96.5,45.3 79.5,45.3 78.5,46.3
IN-
  Top 0.406: R4.2 7,38.8 7.5,38.3 D8.C
  Top 0.5: R17.1 53.5,47.8 53.5,42.8
  pour Top (isolate 1.5): 5.5,44.3 56.5,44.3 56.5,35.8 5.5,35.8
IOBEEP  (via drill 0.6 pad 1, 0.6 pad 1.27)
  Top 0.5: VR1.1 84.51,9.91 v84.5,9.3
  Bottom 0.406: 65.96,28.3 IC1.3
  Bottom 0.5: 65.96,28.3 65,28.3 v65,28.5 64.8,28.3 64,28.3 63,27.8 63,25.3 64.5,23.8 68.5,23.8 73,18.8 75,18.8 79,14.8 79,10.8 80.5,9.3 v84.5,9.3
N$1
  Bottom 0.406: D15.C 48.7,27.65 R5.1 49.05,29.95 R19.2 50,30.3 50,33.56 IC2.6
N$2
  Top 0.5: D3.C 78.72,35.58 79,35.3 79,25.95 79.15,25.8 79.5,25.3 80.1,24.2 80.1,24.05 | 80.1,24.05 R1.1 | Q1.B 80.1,24.05
N$3  (via drill 0.6 pad 1)
  other vias: 75,26
N$4
  Top 0.5: R52.1 31.75,48.25 IC3.8 31,47.99 31,46.3 43.9,46.3 | R12.2 48.8,45.8 D1.C 47.5,46.8 47,46.3 44,46.3 | 43.9,46.3 44,46.3 | 43.9,46.3 C11.+ 43.9,46.2 44,46.3
N$5
  Top 0.5: VBOT.2 63.46,10.75 TRIM.E 67.5,12.34 67.5,14.85 VR4.1
N$6
  Top 0.5: R6.2 87.5,20.3 86.5,21.3 82.5,21.3 82.05,21.75 79.55,21.75 Q1.C
N$7
  Top 0.5: VR46.2 72.6,11.4 74,12.3 TRIM5.S
N$8
  Top 0.5: Q3.B 63.6,44 R3.2
N$9
  Top 0.5: VR2.2 Q10.B
N$10
  Bottom 0.406: IC2.5 53.3,33.7 R21.1 54.4,33.7 55,34.3 55,38.45 R22.1
N$11
  Top 0.5: 56.7,45.8 R15.2 | R12.1 56.7,45.8 | 56.7,45.8 60.5,45.8 60.5,46.7 Q3.C
N$12
  Top 0.5: VR45.2 79.5,7.3 79,6.8 69.23,6.8 TRIM.A
N$13
  Top 0.5: R16.1 35.8,54.1 34.5,52.8 34.5,48.3 36.51,48.3 IC3.1 37.3,48.2 R2.1
N$14
  Top 0.5: TRIM.S 69.4,9.8 VR46.1 70.4,9.4 71.5,8.3 74.15,8.3 IC6.3
N$17
  Bottom 0.406: D15.A 44,25.8 44,38.3 47.09,38.3 IC2.1
N$18
  Top 0.406: R6.1 93.35,20.4 R7.2
N$19
  Top 0.5: R18.1 52.5,49.8 52.5,50.1 R17.2
N$20
  Bottom 0.406: R26.2 43,19.35 | 43,19.35 43,22.3 | 43,22.3 43,44.3 49,44.3 49,38.9 IC2.2 | 43,19.35 43.05,19.4 | 43,22.3 C8.2
N$21
  Bottom 0.406: Q7.B 45.4,49.2 TRIM1.2
N$22
  Bottom 0.406: 53,50.9 R25.2 | 53,50.9 TRIM1.1 53,50 53,50.9 | 53,50.9 R24.1
N$23
  Bottom 0.406: R25.1 R23.2 TRIM1.3
N$24
  Top 0.5: R53.1 29,53.25 R52.2 29.41,50.93 IC3.6
N$25
  Bottom 0.406: D16.C 13.7,29.15 R28.1 14.4,29.3 R29.2 15.4,31.4 15,31.8 15,33.56 IC4.6
N$26
  Bottom 0.406: IC4.5 18.5,33.7 R31.1 18.9,33.7 20,34.3 20,38.75 R32.1
N$27
  Bottom 0.406: Q6.B 10.4,49.9 11.5,48.8 12.3,48.8 TRIM2.2
N$29  (via drill 0.6 pad 1)
  other vias: 65,31.1
N$30
  Bottom 0.406: R35.2 20.2,51.2 R34.1 17.2,50.4 TRIM2.1
N$31
  Bottom 0.406: R35.1 R33.2 TRIM2.3
N$32
  Bottom 0.406: IC4.1 12,38.3 9,38.3 9,26.3 9.5,25.8 D16.A
N$33
  Bottom 0.406: 8,21.8 8,21.3 | 8,21.8 8,44.3 13.5,44.3 14,43.8 14,39.03 IC4.2 | 8.4,21.4 C7.2 | R36.2 7.5,19.8 8.4,20.7 8.4,21.4 | 8.4,21.4 8,21.8
N$34
  Top 0.5: Q10.C 62.9,19.2 62,18.3 61.4,18.3 R60.2
N$35
  Bottom 0.406: D22.C 31.2,29.15 R38.1 31.9,29.3 R39.2 32.64,30.57 IC5.6
N$36
  Bottom 0.406: R42.1 36.5,38.3 37.5,37.8 37.5,34.3 36.5,33.15 R41.1 34.55,33.05 IC5.5
N$37
  Bottom 0.406: Q9.B 27.9,48.9 29,47.8 TRIM3.2
N$38  (via drill 0.6 pad 1.27)
  Top 0.5: v63,13.8 VR2.1
  Bottom 0.5: IC1.2 63.77,31.07 61,29.8 61,24.3 63,21.8 v63,13.8
N$39
  Bottom 0.406: TRIM3.1 34.7,49.9 R44.1 38.2,51.2 R45.2
N$40
  Bottom 0.406: R45.1 R43.2 36.1,46.9 35.5,46.3 34.8,46.3 TRIM3.3
N$41
  Bottom 0.406: D22.A 26.5,25.8 26.5,37.8 27,38.3 29.5,38.3 IC5.1
N$42
  Bottom 0.406: 25.5,22.3 25.5,20.3 25,19.8 R46.2 | 25.5,22.3 25.5,44.3 31.5,44.3 31.5,39.03 IC5.2 | 25.5,22.3 C10.2
N$43
  Top 0.5: TRIM4.3 44.4,56.7 45,56.8 46.55,56.8 R50.2 47.05,56.35 47.5,56.8 49.05,56.8 R49.1
N$45
  Top 0.5: R48.2 51.9,54 51.3,54.3 47.55,54.3 R50.1 45.85,53.75 TRIM4.1
N$46
  Top 0.5: R51.2 26.5,55.3 30.5,55.3 C4.1 | C4.1 31.2,52.9 IC3.5 | R16.2 31.6,55 C4.1
N$47
  Top 0.5: IC3.7 29.64,49.66 29.5,49.8 26.6,49.8 R51.1 26.5,47.3 22,47.3 21.96,47.26 Q2.1
ONEWIRE  (via drill 0.6 pad 1.27)
  Top 0.4: 68.85,34.3 U$2.4
  Top 0.406: v69.5,35.3 68.85,34.65 68.85,34.3
  Top 0.5: v69.5,35.3 R13.2
  Bottom 0.406: 69.5,35.8 v69.5,35.3 | 73.62,25.8 IC1.5
  Bottom 0.5: 73.62,25.8 70.5,25.8 69.5,26.8 69.5,35.8
PANEL-
  Top 0.5: 37.5,57.3 41.5,57.3 42,56.8 42,52.3 43,51.3 43.1,51.3 C11.- 43.7,50.6 43.5,50.8 47.2,50.8 D1.A | 37.5,57.3 32,57.3 31.7,57 C4.2 31.15,56.85 R53.2 28.45,56.8 PANEL-.1 21.89,56.69 Q2.3 | IC3.4 37.1,52.4 37.5,52.8 37.5,57.3 | D1.A 47.3,50.3 | D1.A R18.2 49.5,49.9 R49.2
R
  pour Top (isolate 1, rank 3, no thermals): 81.25,35.8 83,35.8 83,31.3 81.25,31.3
UV
  Bottom 0.406: Q7.C 50.5,50.8 50.5,45.8 51.5,44.8 53,44.8 54,43.3 R22.2 54,42.05
UV2
  Bottom 0.406: Q9.C 32,50.8 32.5,50.3 32.5,45.3 33,44.8 35.2,44.8 35.5,44.2 35.5,43.8 36,43.3 36,42.35 R42.2
UV3
  Bottom 0.406: Q6.C 14,51.8 15,50.8 15,45.3 15.5,44.8 17.5,44.8 18,44.3 18,43.8 19,42.8 R32.2 19,42.05
VDD  (via drill 0.6 pad 1, 0.6 pad 1.5, 1 pad 1.78)
  Top 0.4: U$2.5 68,32.3 IC1.1 66,33.8
  Top 0.406: SP3.- 91.75,16.05
  Top 0.5: U$1.5 v91.5,40.3 | R48.1 55,52.8 57,54.8 P(+)1.1 57.5,55.3 R15.1 | TRIM5.E 71.56,15.09 VR4.2 74.55,18.8 74.55,19.75 74,20.3 66.5,20.3 | IC6.5 77.3,10.6 78.5,12.3 78.5,19.3 | 66,33.8 65.1,33.8 v65,33.7
  Bottom 0.406: R20.2 43,45.85 43,52.8 | 43,52.8 44,53.3 | 44,53.3 50.9,53.3 R24.2 55.9,53.4 66.5,53.3 v67.5,54.8 61,53.8 | Q7.E 45.4,52.7 44,53.3 | R30.2 9.95,46.8 9,46.8 8,47.8 8,53.8 9.5,53.8 10.4,52.9 Q6.E 10.5,52.85 10.5,53.3 11,53.8 17.5,53.8 17.9,53.4 R34.2 18.9,52.8 25.5,52.8 | R40.2 25.55,45.85 25.5,45.8 25.5,52.8 | 25.5,52.8 27.35,52.8 Q9.E 28,51.85 28,52.3 28.5,52.8 33,52.8 34.1,53.4 R44.2 37.1,52.8 43,52.8
  Bottom 0.5: 55.9,53.4 56.6,53.4 58,54.8 P(+)1.1
  other vias: 79.1,43.1 81.8,43.1
  pour Top (isolate 1.5, rank 3): 76.5,43.05 76.5,56.3 72.5,56.3 72.5,59.8 59.5,59.8 59.5,52.8 60.5,51.3 60.5,15.3 92.5,14.8 92.5,16.3 66.5,26.3 67,33.8 67.5,34.3 71.5,38.8 72.5,38.3 96.5,37.8 96.5,43.05
  pour Bottom (isolate 1.5, rank 2): 76.5,43.8 76.5,56.3 60.5,56.3 60.5,31.8 67,31.8 67,33.8 67.5,34.3 71.5,38.8 72.5,38.3 96.5,38.3 96.5,43.8
VDD1
  Bottom 0.406: D2.C R20.1 45,40.35 R27.1
VDD2
  Bottom 0.406: R38.2 27.95,35.2 R47.2 | IC5.8 30.09,34.2 28,35.3 R47.2 | C9.2 28.45,36.3 R47.2
VSS  (via drill 0.6 pad 1, 0.6 pad 1.27, 0.6 pad 1.5)
  Top 0.4: U$2.2 72,32.3
  Top 0.406: 72,32.3 IC1.8
  Top 0.5: v91.5,34.3 U$1.2 | Q1.E 77.75,25.3 77.75,32.3 77.5,32.3 76,33.8 | 76,33.8 C2.- | 76,33.8 v76.8,33.3 | IC6.2 IC6.1 74.45,10.25 76.5,12.3 76.5,13.53 TRIM5.A 77.04,16.71 R14.1 | C3.- 92,32.8 v91.5,33.3
  Bottom 0.5: 91.5,25.3 v91.5,34.3 | TRIM5.A 77.04,12.34 76,11.3 75.25,11.3 74.2,10.25 | v76.8,33.3 v75,33.6
  pour Bottom (isolate 1.5, rank 5): 73,35.3 80,35.3 80,25.55 96.5,25.55 96.5,9.3 92,4.3 62,4.3 60.5,8.8 60.5,22.8 73.5,22.8 76,25.3 76,30.8 73.5,30.8 73,31.3
  pour Top (isolate 1): 73,36.8 78,36.8 78,32.3 73,32.3 73,35.3
  pour Bottom (isolate 1, rank 5): 81.5,35.3 96.5,35.3 96.5,26.8 81.5,26.8
XXX
  Bottom 0.406: C5.2 47.9,36.3 47.5,35.8 47.5,34.8 | 47.5,34.8 47.5,33.79 IC2.8 | R5.2 45.5,33.8 46,34.8 46.5,34.8 | 46.5,34.8 47.5,34.8 | R27.2 45.5,35.8 46.5,34.8
XXY
  Bottom 0.406: C6.2 10.95,36.3 R37.2 | R28.2 10.45,36.7 R37.2 | IC4.8 12.6,34.65 R37.2

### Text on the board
tTest: 4v4
Document: 1m | 10u | 10u | 300u | 2mA | 500u | 1m | 2m | 300u | 300u | 30u | 5m | 14m | 12m | 500u | 5m | 5m | 5m | 5m | 5m | 5m | 40m | 40m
